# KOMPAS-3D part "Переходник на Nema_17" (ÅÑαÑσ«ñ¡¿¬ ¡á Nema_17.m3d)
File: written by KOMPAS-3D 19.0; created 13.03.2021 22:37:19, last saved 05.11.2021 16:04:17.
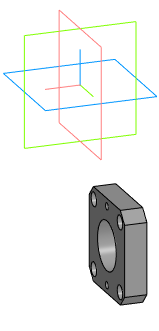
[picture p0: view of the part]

Document properties: Автор: Agent Smith; Полное имя файла: D:\3D_print\3D проекты Компас 3D\Халява Projects 5\Переходник на Nema_17.m3d

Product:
- Part/product: Переходник на Nema_17
    Масса: 0.0956301

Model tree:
1. Эскиз:1  (with: Элемент выдавливания:9)  (labels: Переходник на Nema_17)
2. Элемент выдавливания:1
     Расстояние 1 = 6
3. Эскиз:2  (with: Элемент выдавливания:1)
4. Элемент выдавливания:2
     Расстояние 2 = 3
5. Эскиз:3  (with: Элемент выдавливания:1)
6. Элемент выдавливания:3
     Расстояние 2 = 3
7. Элемент выдавливания:4  (with: Элемент выдавливания:1)
     Расстояние 1 = 2
8. Элемент выдавливания:5  (with: Элемент выдавливания:4, Элемент выдавливания:11)  (labels: Переходник на Nema_17)
     Расстояние 1 = 2

Referenced files in D:\3D_print\3D проекты Компас 3D\Редуктор (Снова)\: Намоточный станок (Projects 6).a3d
